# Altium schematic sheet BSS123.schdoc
size 127 x 101 mm
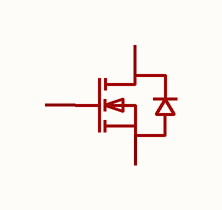
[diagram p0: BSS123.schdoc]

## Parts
Q?  bss123_c79015  [SOT-23-3_L2.9-W1.6-P1.90-LS2.8-BR]  (value not drawn)

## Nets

Not connected (* = marked no-connect by the designer): Q? 1(G) 2(S) 3(D)

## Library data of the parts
Q? = bss123_c79015: 数量:1个N沟道;漏源电压(Vdss):100V;连续漏极电流(Id):170mA;导通电阻(RDS(on)):6Ω@10V;耗散功率(Pd):350mW;阈值电压(Vgs(th)):2.8V;; Manufacturer: CJ(江苏长电/长晶); Symbol: BSS123; AddInBom: yes; ModelId: 89cb27a44ab2466697082bb9fd73a7d0; ModelName: SOT-23-3L_L2.9-W1.6-H1.1-LS2.8-P0.95; ModelTransform: 114.173,110.236,0,90,0,0,0,0,0; Number: 1个N沟道; Drain to Source Voltage: 100V; Current - Continuous Drain(Id): 170mA; RDS(on): 6Ω@10V; Pd - Power Dissipation: 350mW; Gate Threshold Voltage (Vgs(th)): 2.8V; Gate Charge(Qg): 1.4nC; Input Capacitance(Ciss): 29pF; Reverse Transfer Capacitance (Crss@Vds): 2pF; Type: N沟道; Output Capacitance(Coss): 15pF; Vgs: ±20V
